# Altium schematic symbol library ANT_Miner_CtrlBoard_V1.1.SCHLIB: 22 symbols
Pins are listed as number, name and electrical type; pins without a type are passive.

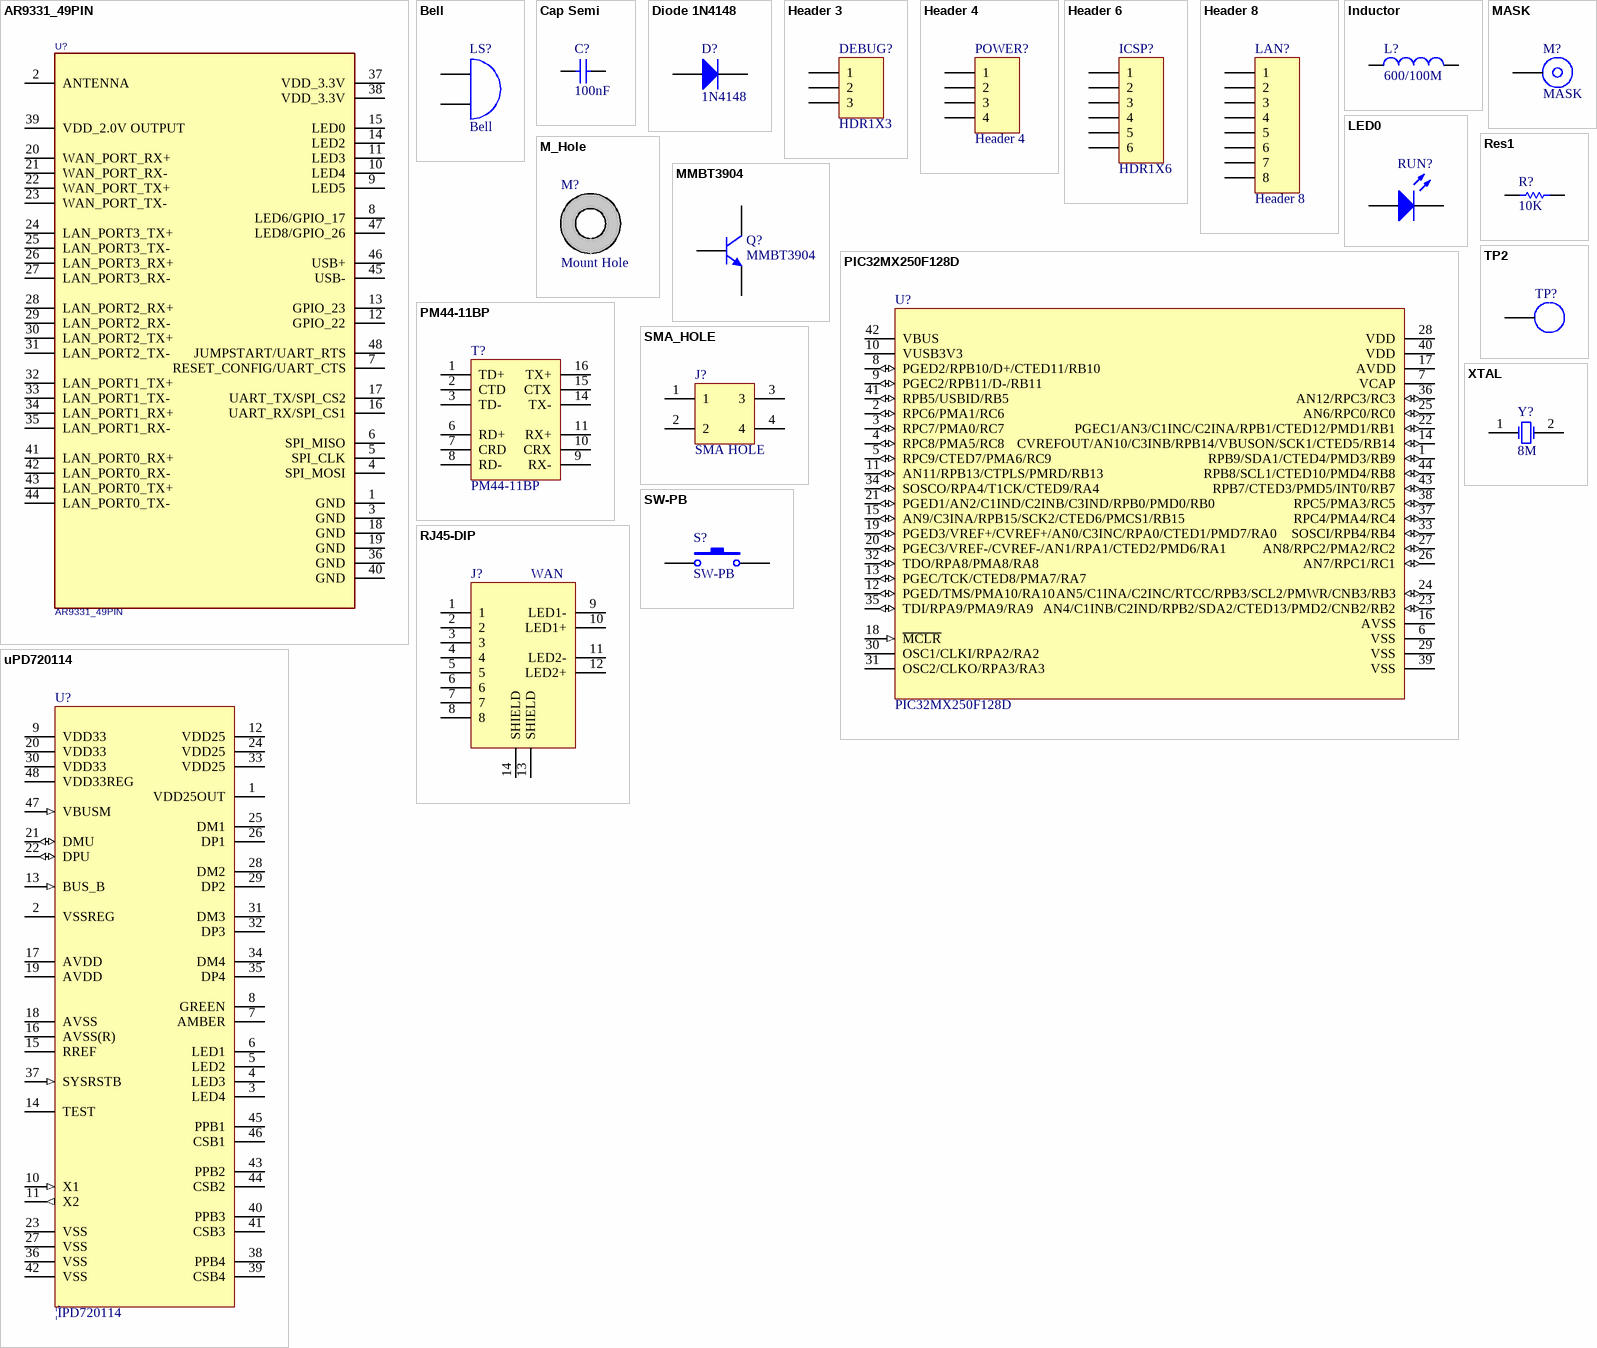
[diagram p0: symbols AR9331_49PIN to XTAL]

## AR9331_49PIN
designator U?
footprint AR9331_49PIN (AR9331 49PIN)
pins: 1 GND, 2 ANTENNA, 3 GND, 4 SPI_MOSI, 5 SPI_CLK, 6 SPI_MISO, 7 RESET_CONFIG/UART_CTS, 8 LED6/GPIO_17, 9 LED5, 10 LED4, 11 LED3, 12 GPIO_22, 13 GPIO_23, 14 LED2, 15 LED0, 16 UART_RX/SPI_CS1, 17 UART_TX/SPI_CS2, 18 GND, 19 GND, 20 WAN_PORT_RX+, 21 WAN_PORT_RX-, 22 WAN_PORT_TX+, 23 WAN_PORT_TX-, 24 LAN_PORT3_TX+, 25 LAN_PORT3_TX-, 26 LAN_PORT3_RX+, 27 LAN_PORT3_RX-, 28 LAN_PORT2_RX+, 29 LAN_PORT2_RX-, 30 LAN_PORT2_TX+, 31 LAN_PORT2_TX-, 32 LAN_PORT1_TX+, 33 LAN_PORT1_TX-, 34 LAN_PORT1_RX+, 35 LAN_PORT1_RX-, 36 GND, 37 VDD_3.3V, 38 VDD_3.3V, 39 VDD_2.0V OUTPUT, 40 GND, 41 LAN_PORT0_RX+, 42 LAN_PORT0_RX-, 43 LAN_PORT0_TX+, 44 LAN_PORT0_TX-, 45 USB-, 46 USB+, 47 LED8/GPIO_26, 48 JUMPSTART/UART_RTS
2 alternate drawings of the same symbol

## Bell
designator LS?
Electrical Bell
footprint YR5025A
pins: 1 A, 2 B

## Cap Semi
designator C?, comment 100nF
Capacitor (Semiconductor SIM Model)
footprint CC0603(1608) (Chip Capacitor, Body 1.6x0.8mm, IPC High Density)
pins: 1, 2

## Diode 1N4148
designator D?, comment 1N4148
High Conductance Fast Diode
signal-integrity model 1N4148
footprint DIODE0805
pins: 1 A, 2 K

## Header 3
designator DEBUG?, comment HDR1X3
Header, 3-Pin
signal-integrity model Connector
footprint HDR1X3 (Connector; Header; 3 Position)
pins: 1, 2, 3

## Header 4
designator POWER?
Header, 4-Pin
signal-integrity model Connector
footprint 4PIN_180
pins: 1, 2, 3, 4

## Header 6
designator ICSP?, comment HDR1X6
Header, 6-Pin
signal-integrity model Connector
footprint HDR1X6 (Connector; Header; 6 Position)
pins: 1, 2, 3, 4, 5, 6

## Header 8
designator LAN?
Header, 8-Pin
signal-integrity model Connector
footprint 8PIN_180
pins: 1, 2, 3, 4, 5, 6, 7, 8

## Inductor
designator L?, comment 600/100M
Inductor; Code_IEC: 1005
simulation model INDUCTOR (Inductor)
signal-integrity model Inductor
footprint INDC1608L (Chip Inductor, Body 1.6x0.8mm, IPC High Density)
pins: 1, 2

## LED0
designator RUN?, comment Green  (value not drawn)
Typical INFRARED GaAs LED
simulation model LED0 (Diode)
footprint LED0603(1608) (Chip LED, Body 1.6x0.8mm, IPC High Density)
pins: 1 A, 2 K

## M_Hole
designator M?, comment Mount Hole
footprint HOLE_3.2
pins: 0 PIN (power)

## MASK
designator M?
footprint MASK (SMD MASK 1mm)
pins: 1

## MMBT3904
designator Q?
NPN Switching Transistor
simulation model QMMBT3904 (NPN)
footprint SOT23_L (SOT23, 3-Leads, Body 2.9x1.3mm, Pitch 0.95mm, Lead Span 2.3mm - Reverse Pinning, IPC High Density)
pins: 1 B, 2 E, 3 C

## PIC32MX250F128D
designator U?
footprint TQFP44_L (Thin QFP, 44-Leads, Body 10x10mm, Pitch 0.8mm, IPC High Density)
pins: 1 RPB9/SDA1/CTED4/PMD3/RB9 (io), 2 RPC6/PMA1/RC6 (io), 3 RPC7/PMA0/RC7 (io), 4 RPC8/PMA5/RC8 (io), 5 RPC9/CTED7/PMA6/RC9 (io), 6 VSS (power), 7 VCAP (power), 8 PGED2/RPB10/D+/CTED11/RB10 (io), 9 PGEC2/RPB11/D-/RB11 (io), 10 VUSB3V3 (power), 11 AN11/RPB13/CTPLS/PMRD/RB13 (io), 12 PGED/TMS/PMA10/RA10 (io), 13 PGEC/TCK/CTED8/PMA7/RA7 (io), 14 CVREFOUT/AN10/C3INB/RPB14/VBUSON/SCK1/CTED5/RB14 (io), 15 AN9/C3INA/RPB15/SCK2/CTED6/PMCS1/RB15 (io), 16 AVSS (power), 17 AVDD (power), 18 ~{MCLR} (in), 19 PGED3/VREF+/CVREF+/AN0/C3INC/RPA0/CTED1/PMD7/RA0 (io), 20 PGEC3/VREF-/CVREF-/AN1/RPA1/CTED2/PMD6/RA1 (io), 21 PGED1/AN2/C1IND/C2INB/C3IND/RPB0/PMD0/RB0 (io), 22 PGEC1/AN3/C1INC/C2INA/RPB1/CTED12/PMD1/RB1 (io), 23 AN4/C1INB/C2IND/RPB2/SDA2/CTED13/PMD2/CNB2/RB2 (io), 24 AN5/C1INA/C2INC/RTCC/RPB3/SCL2/PMWR/CNB3/RB3 (io), 25 AN6/RPC0/RC0 (io), 26 AN7/RPC1/RC1 (io), 27 AN8/RPC2/PMA2/RC2 (io), 28 VDD (power), 29 VSS (power), 30 OSC1/CLKI/RPA2/RA2, 31 OSC2/CLKO/RPA3/RA3, 32 TDO/RPA8/PMA8/RA8 (io), 33 SOSCI/RPB4/RB4 (io), 34 SOSCO/RPA4/T1CK/CTED9/RA4 (io), 35 TDI/RPA9/PMA9/RA9 (io), 36 AN12/RPC3/RC3 (io), 37 RPC4/PMA4/RC4 (io), 38 RPC5/PMA3/RC5 (io), 39 VSS (power), 40 VDD (power), 41 RPB5/USBID/RB5 (io), 42 VBUS (power), 43 RPB7/CTED3/PMD5/INT0/RB7 (io), 44 RPB8/SCL1/CTED10/PMD4/RB8 (io)

## PM44-11BP
designator T?
footprint PM44-11BP
pins: 1 TD+, 2 CTD, 3 TD-, 6 RD+, 7 CRD, 8 RD-, 9 RX-, 10 CRX, 11 RX+, 14 TX-, 15 CTX, 16 TX+

## Res1
designator R?, comment 10K
Resistor
footprint RR0603(1608) (Chip Resistor, Body 1.6x0.8mm, IPC High Density)
pins: 1, 2

## RJ45-DIP
designator J?, comment WAN
RJ45,DUAL LED,DIP
footprint RJ45_2LED_DIP
pins: 1, 2, 3, 4, 5, 6, 7, 8, 9 LED1-, 10 LED1+, 11 LED2-, 12 LED2+, 13 SHIELD, 14 SHIELD

## SMA_HOLE
designator J?, comment SMA HOLE
SMA Socket Assembly Hole.
footprint SMA_HOLE (SMA Socket Assembly Hole.)
pins: 1, 2, 3, 4

## SW-PB
designator S?
Switch
footprint SWITCH_3x4
pins: 1, 2

## TP2
designator TP?, comment TP  (value not drawn)
footprint TP2 (Test Point 2mm SMD)
pins: 1

## uPD720114
designator U?, comment ¦ÌPD720114
footprint TQFP48_L
pins: 1 VDD25OUT (power), 2 VSSREG (power), 3 LED4, 4 LED3, 5 LED2, 6 LED1, 7 AMBER, 8 GREEN, 9 VDD33 (power), 10 X1 (in), 11 X2 (out), 12 VDD25 (power), 13 BUS_B (in), 14 TEST, 15 RREF, 16 AVSS(R) (power), 17 AVDD (power), 18 AVSS (power), 19 AVDD (power), 20 VDD33 (power), 21 DMU (io), 22 DPU (io), 23 VSS (power), 24 VDD25 (power), 25 DM1, 26 DP1, 27 VSS (power), 28 DM2, 29 DP2, 30 VDD33 (power), 31 DM3, 32 DP3, 33 VDD25 (power), 34 DM4, 35 DP4, 36 VSS (power), 37 SYSRSTB (in), 38 PPB4, 39 CSB4, 40 PPB3, 41 CSB3, 42 VSS (power), 43 PPB2, 44 CSB2, 45 PPB1, 46 CSB1, 47 VBUSM (in), 48 VDD33REG (power)

## XTAL
designator Y?, comment 8M
Crystal Oscillator
simulation model XTAL (Spice Subcircuit)
footprint 4SMX
pins: 1 OSC1, 2 OSC2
